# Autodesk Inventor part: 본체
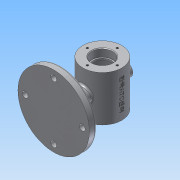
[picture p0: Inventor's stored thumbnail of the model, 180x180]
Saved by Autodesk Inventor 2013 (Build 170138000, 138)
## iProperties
Created: 2018-12
Part Number: 본체
Material: 알루미늄 6061
Document SubType Name: Modeling
Designer: Administrator
Density: 2.71 g/cm^3
Mass: 687.624 g
Surface Area: 555.495 cm^2
Volume: 253.736 cm^3
Author: Administrator
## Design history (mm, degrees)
sketch "스케치1"
  geometry: C1 r 30 at (0, 0); 1 further point
  constraints: 1 centre point, 1 coincident
  dimensions: "d0" = 60 diameter of C1
extrude "돌출1" new body sketch "스케치1" distance "d1" = 35; taper "d2" = 0 deg
hole "구멍1" diameter "d5" = 50; stored, may be unused: countersink angle "d9" = 90 deg, drill point angle "d11" = 0 deg; dims "d3" = 10, "d4" = 10, "d6" = 6, "d7" = 4, "d8" = 2, "d10" = 20
hole "구멍2" diameter "d14" = 28; stored, may be unused: countersink angle "d18" = 90 deg, drill point angle "d20" = 0 deg; dims "d12" = 10, "d13" = 10, "d15" = 6, "d16" = 32, "d17" = 12, "d19" = 20
sketch "스케치2"
  geometry: 2 further points
  constraints: 1 vertical alignment
  dimensions: "d21" = 23 distance of point (0, 23) point (0, 0)
hole "구멍3" sketch "스케치2" at (0, 23) diameter "d22" = 3.242; stored, may be unused: countersink angle "d26" = 90 deg, drill point angle "d28" = 118 deg; dims "d23" = 8, "d24" = 32, "d25" = 12, "d27" = 10
chamfer "모따기1" distance "d32" = 1; stored, may be unused: second distance "d33" = 2, angle "d34" = 45 deg
fillet "모깎기1" dims "d35" = 0.3
fillet "모깎기2" dims "d36" = 3
node "작업 평면1"
sketch "스케치3"
  geometry: C1 r 55 at (0, 0); 1 further point
  constraints: 1 centre point, 1 coincident
  dimensions: "d38" = 110 diameter of C1
extrude "돌출2" join sketch "스케치3" distance "d39" = 11; taper "d40" = 0 deg
sketch "스케치4"
  geometry: C1 r 12 at (0, 0); 1 further point
  constraints: 1 centre point, 1 coincident
  dimensions: "d41" = 24 diameter of C1
extrude "돌출3" join sketch "스케치4" stored distance "d42" = 10; taper "d43" = 0 deg
sketch "스케치6"
  geometry: C1 r 55 at (0, 0) reference; 1 further point
extrude "돌출4" join sketch "스케치6" distance "d44" = 13; taper "d45" = -75 deg
sketch "스케치7"
  geometry: 2 further points
  constraints: 1 vertical alignment
  dimensions: "d46" = 44 distance of point (0, 44) point (0, 0)
hole "구멍4" sketch "스케치7" at (0, 44) diameter "d47" = 9; stored, may be unused: countersink angle "d51" = 90 deg, drill point angle "d53" = 0 deg; dims "d48" = 8, "d49" = 32, "d50" = 12, "d52" = 10
hole "구멍6" diameter "d65" = 14; stored, may be unused: countersink angle "d69" = 90 deg, drill point angle "d71" = 0 deg; dims "d63" = 10, "d64" = 10, "d66" = 8, "d67" = 32, "d68" = 12, "d70" = 30
node "작업 평면2"
sketch "스케치8"
  geometry: C1 r 10 at (0, 0); 1 further point
  constraints: 1 centre point, 1 coincident
  dimensions: "d76" = 20 diameter of C1
extrude "돌출5" join sketch "스케치8" stored distance "d77" = 13; taper "d78" = 0 deg
hole "구멍7" diameter "d81" = 10; stored, may be unused: countersink angle "d85" = 90 deg, drill point angle "d87" = 0 deg; dims "d79" = 10, "d80" = 10, "d82" = 8, "d83" = 32, "d84" = 12, "d86" = 30
fillet "모깎기3" dims "d88" = 3
node "작업 평면3"
sketch "스케치9"
  geometry: L1 (30, 35)-(-30, 35) reference; L2 (30, -35)-(30, 35) reference; 2 further points
  constraints: 1 other
  dimensions: "d90" = 35 distance from line of point (0, 0) L1; "d91" = 30 distance from line of point (0, 0) L2
feature "엠보싱1" sketch "스케치9" dims "d32" = 1, "d92" = 0.5, "d93" = 0
chamfer "모따기2" distance "d94" = 1; stored, may be unused: second distance "d95" = 2, angle "d96" = 45 deg
node "솔리드1"
pattern_circular "원형 패턴1" dims angle "d30" = 360 deg
mirror "대칭1"
pattern_circular "원형 패턴2" dims angle "d73" = 360 deg
other parameters: "d37" = -75, "d75" = -112, "d89" = 104
